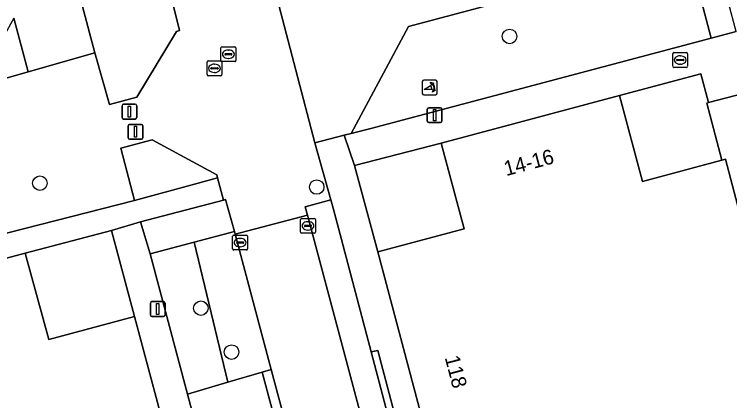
# Model space of a CAD drawing. Extents: x 162542 to 163147, y 380779 to 381521.
# Drawn here: x 162623.92 to 162672.17, y 381152.86 to 381178.9 of the extents above; entities that cross this region are included whole.
import ezdxf

# ---------------------------------------------------------------- set-up
doc = ezdxf.new("R2010")
doc.units = 0
for name, color, linetype in [('IMGEO_Afsluitpaal', 7, 'Continuous'), ('IMGEO_Boom', 7, 'Continuous'), ('IMGEO_Brandkraan', 7, 'Continuous'), ('IMGEO_Erf', 7, 'Continuous'), ('IMGEO_Groenvoorziening', 7, 'Continuous'), ('IMGEO_Kolk', 7, 'Continuous'), ('IMGEO_Lichtmast', 7, 'Continuous'), ('IMGEO_Muur', 7, 'Continuous'), ('IMGEO_Pand', 7, 'Continuous'), ('IMGEO_Pand_nummerreeks', 7, 'Continuous'), ('IMGEO_Parkeervlak_open', 7, 'Continuous'), ('IMGEO_Poller', 7, 'Continuous'), ('IMGEO_Rijbaan_lokaal_open', 7, 'Continuous'), ('IMGEO_Rioolput', 7, 'Continuous'), ('IMGEO_Voetpad_open', 7, 'Continuous')]:
    doc.layers.add(name, color=color, linetype=linetype)

msp = doc.modelspace()

# ---------------------------------------------------------------- linework, layer by layer
at = {"layer": 'IMGEO_Afsluitpaal'}
for p, q in [((162631.183, 381171.945), (162631.183, 381172.745)), ((162631.183, 381172.745), (162631.183, 381171.945)), ((162631.283, 381172.845), (162632.073, 381172.845)), ((162632.073, 381172.845), (162631.283, 381172.845)), ((162632.173, 381172.745), (162632.173, 381171.945)), ((162632.173, 381171.945), (162632.173, 381172.745)), ((162632.073, 381171.845), (162631.283, 381171.845)), ((162631.283, 381171.845), (162632.073, 381171.845)), ((162631.697, 381171.488), (162632.487, 381171.488)), ((162632.487, 381171.488), (162631.697, 381171.488)), ((162631.597, 381170.588), (162631.597, 381171.388)), ((162631.597, 381171.388), (162631.597, 381170.588)), ((162632.587, 381171.388), (162632.587, 381170.588)), ((162632.587, 381170.588), (162632.587, 381171.388)), ((162632.487, 381170.488), (162631.697, 381170.488)), ((162631.697, 381170.488), (162632.487, 381170.488))]:
    msp.add_line(p, q, dxfattribs=at)
for points in [[(162631.603, 381172.72), (162631.753, 381172.72), (162631.753, 381171.97), (162631.603, 381171.97), (162631.603, 381172.72)], [(162632.017, 381171.363), (162632.167, 381171.363), (162632.167, 381170.613), (162632.017, 381170.613), (162632.017, 381171.363)]]:
    msp.add_lwpolyline(points, dxfattribs=at)
for centre, start, end in [((162631.283, 381172.745), 90, 180), ((162631.283, 381172.745), 90, 180), ((162632.073, 381172.745), 0, 90), ((162632.073, 381172.745), 360, 90), ((162631.283, 381171.945), 180, 270), ((162631.283, 381171.945), 180, 270), ((162632.073, 381171.945), 270, 0), ((162632.073, 381171.945), 270, 0), ((162631.697, 381171.388), 90, 180), ((162631.697, 381171.388), 90, 180), ((162632.487, 381171.388), 0, 90), ((162632.487, 381171.388), 360, 90), ((162631.697, 381170.588), 180, 270), ((162631.697, 381170.588), 180, 270), ((162632.487, 381170.588), 270, 0), ((162632.487, 381170.588), 270, 0)]:
    msp.add_arc(centre, 0.1, start, end, dxfattribs=at)
at = {"layer": 'IMGEO_Boom'}
for centre in [(162657.326, 381177.414), (162625.643, 381167.524), (162644.318, 381167.263), (162636.502, 381159.099), (162638.572, 381156.14)]:
    msp.add_circle(centre, 0.489, dxfattribs=at)
at = {"layer": 'IMGEO_Brandkraan'}
for p, q in [((162668.336, 381175.398), (162668.336, 381176.25)), ((162668.411, 381176.324), (162669.263, 381176.324)), ((162669.337, 381176.25), (162669.337, 381175.398)), ((162668.595, 381175.818), (162668.595, 381175.83)), ((162669.033, 381175.781), (162668.635, 381175.781)), ((162668.638, 381175.867), (162669.036, 381175.867)), ((162668.824, 381176.104), (162668.849, 381176.104)), ((162669.079, 381175.83), (162669.079, 381175.818)), ((162669.263, 381175.324), (162668.411, 381175.324)), ((162668.847, 381175.544), (162668.822, 381175.544))]:
    msp.add_line(p, q, dxfattribs=at)
for points in [[(162668.336, 381175.398), (162668.336, 381176.25)], [(162668.411, 381176.324), (162669.263, 381176.324)], [(162669.337, 381176.25), (162669.337, 381175.398)], [(162669.263, 381175.324), (162668.411, 381175.324)]]:
    msp.add_lwpolyline(points, dxfattribs=at)
for centre, radius, start, end in [((162668.413, 381176.248), 0.0765, 91.552, 178.448), ((162668.413, 381176.248), 0.0765, 91.552, 178.448), ((162669.261, 381176.248), 0.0765, 1.552, 88.448), ((162669.261, 381176.248), 0.0765, 1.552, 88.448), ((162668.635, 381175.827), 0.0403, 85.8775, 175.7526), ((162668.632, 381175.817), 0.0366, 178.938, 274.7102), ((162669.036, 381175.824), 0.043, 264.8664, 352.4533), ((162669.04, 381175.829), 0.0386, 1.7309, 96.639), ((162668.413, 381175.4), 0.0765, 181.552, 268.448), ((162668.413, 381175.4), 0.0765, 181.552, 268.448), ((162669.261, 381175.4), 0.0765, 271.552, 358.448), ((162669.261, 381175.4), 0.0765, 271.552, 358.448)]:
    msp.add_arc(centre, radius, start, end, dxfattribs=at)
for centre, major_axis, ratio, start_param, end_param in [((162668.823, 381175.824), (-0.387, 0.002), 0.722429, 4.712389, 7.853982), ((162668.848, 381175.824), (-0.39, 0.002), 0.717154, 1.570796, 4.712389)]:
    msp.add_ellipse(centre, major_axis=major_axis, ratio=ratio, start_param=start_param, end_param=end_param, dxfattribs=at)
at = {"layer": 'IMGEO_Erf'}
for points in [[(162670.743, 381172.955), (162670.222, 381174.901), (162664.741, 381173.435), (162666.29, 381167.639), (162671.652, 381169.072), (162670.628, 381172.925)], [(162646.862, 381168.708), (162648.45, 381162.897), (162654.253, 381164.438), (162652.708, 381170.219)], [(162630.483, 381164.337), (162624.653, 381162.805), (162626.236, 381156.981), (162632.03, 381158.534)]]:
    msp.add_lwpolyline(points, close=True, dxfattribs=at)
at = {"layer": 'IMGEO_Groenvoorziening'}
for points in [[(162632.502, 381187.604), (162626.664, 381186.379), (162629.355, 381176.297), (162630.35, 381172.815), (162632.19, 381173.314), (162634.858, 381177.742), (162635.064, 381177.813), (162634.81, 381178.822), (162634.471, 381180.17)], [(162670.936, 381177.305), (162669.386, 381183.119), (162650.506, 381178.074), (162646.633, 381170.872), (162647.97, 381171.219)], [(162636.076, 381167.451), (162637.632, 381167.876), (162637.578, 381168.082), (162633.212, 381170.434), (162631.108, 381169.893), (162632.035, 381166.352)], [(162638.813, 381164.087), (162638.764, 381164.265), (162636.059, 381163.549), (162638.324, 381154.112), (162640.636, 381154.797), (162641.237, 381154.972)], [(162636.059, 381163.549), (162633.072, 381162.758), (162635.59, 381153.303), (162638.324, 381154.112)]]:
    msp.add_lwpolyline(points, close=True, dxfattribs=at)
at = {"layer": 'IMGEO_Kolk'}
for p, q in [((162643.301, 381165.145), (162644.153, 381165.145)), ((162643.226, 381164.219), (162643.226, 381165.071)), ((162643.528, 381164.688), (162643.926, 381164.688)), ((162643.714, 381164.925), (162643.739, 381164.925)), ((162644.227, 381165.071), (162644.227, 381164.219)), ((162643.485, 381164.639), (162643.485, 381164.651)), ((162643.923, 381164.602), (162643.525, 381164.602)), ((162643.737, 381164.365), (162643.712, 381164.365)), ((162643.969, 381164.651), (162643.969, 381164.639)), ((162638.647, 381163.094), (162638.647, 381163.946)), ((162638.722, 381164.02), (162639.574, 381164.02)), ((162639.135, 381163.8), (162639.16, 381163.8)), ((162639.648, 381163.946), (162639.648, 381163.094)), ((162644.153, 381164.145), (162643.301, 381164.145)), ((162638.906, 381163.514), (162638.906, 381163.526)), ((162639.344, 381163.477), (162638.946, 381163.477)), ((162638.949, 381163.563), (162639.347, 381163.563)), ((162639.158, 381163.24), (162639.133, 381163.24)), ((162639.39, 381163.526), (162639.39, 381163.514)), ((162639.574, 381163.02), (162638.722, 381163.02))]:
    msp.add_line(p, q, dxfattribs=at)
for points in [[(162643.301, 381165.145), (162644.153, 381165.145)], [(162643.226, 381164.219), (162643.226, 381165.071)], [(162644.227, 381165.071), (162644.227, 381164.219)], [(162638.647, 381163.094), (162638.647, 381163.946)], [(162638.722, 381164.02), (162639.574, 381164.02)], [(162639.648, 381163.946), (162639.648, 381163.094)], [(162644.153, 381164.145), (162643.301, 381164.145)], [(162639.574, 381163.02), (162638.722, 381163.02)]]:
    msp.add_lwpolyline(points, dxfattribs=at)
for centre, radius, start, end in [((162643.303, 381165.069), 0.0765, 91.552, 178.448), ((162643.303, 381165.069), 0.0765, 91.552, 178.448), ((162644.151, 381165.069), 0.0765, 1.552, 88.448), ((162644.151, 381165.069), 0.0765, 1.552, 88.448), ((162643.525, 381164.648), 0.0403, 85.8775, 175.7526), ((162643.93, 381164.65), 0.0386, 1.7309, 96.639), ((162643.303, 381164.221), 0.0765, 181.552, 268.448), ((162643.303, 381164.221), 0.0765, 181.552, 268.448), ((162643.522, 381164.638), 0.0366, 178.938, 274.7102), ((162643.926, 381164.645), 0.043, 264.8664, 352.4533), ((162644.151, 381164.221), 0.0765, 271.552, 358.448), ((162644.151, 381164.221), 0.0765, 271.552, 358.448), ((162638.724, 381163.944), 0.0765, 91.552, 178.448), ((162638.724, 381163.944), 0.0765, 91.552, 178.448), ((162639.572, 381163.944), 0.0765, 1.552, 88.448), ((162639.572, 381163.944), 0.0765, 1.552, 88.448), ((162638.946, 381163.523), 0.0403, 85.8775, 175.7526), ((162638.943, 381163.513), 0.0366, 178.938, 274.7102), ((162639.347, 381163.52), 0.043, 264.8664, 352.4533), ((162639.351, 381163.525), 0.0386, 1.7309, 96.639), ((162638.724, 381163.096), 0.0765, 181.552, 268.448), ((162638.724, 381163.096), 0.0765, 181.552, 268.448), ((162639.572, 381163.096), 0.0765, 271.552, 358.448), ((162639.572, 381163.096), 0.0765, 271.552, 358.448)]:
    msp.add_arc(centre, radius, start, end, dxfattribs=at)
for centre, major_axis, ratio, start_param, end_param in [((162643.713, 381164.645), (-0.387, 0.002), 0.722429, 4.712389, 7.853982), ((162643.738, 381164.645), (-0.39, 0.002), 0.717154, 1.570796, 4.712389), ((162639.134, 381163.52), (-0.387, 0.002), 0.722429, 4.712389, 7.853982), ((162639.159, 381163.52), (-0.39, 0.002), 0.717154, 1.570796, 4.712389)]:
    msp.add_ellipse(centre, major_axis=major_axis, ratio=ratio, start_param=start_param, end_param=end_param, dxfattribs=at)
at = {"layer": 'IMGEO_Lichtmast'}
for p, q in [((162651.773, 381171.707), (162651.773, 381172.507)), ((162651.773, 381172.507), (162651.773, 381171.707)), ((162651.873, 381172.607), (162652.663, 381172.607)), ((162652.663, 381172.607), (162651.873, 381172.607)), ((162652.763, 381172.507), (162652.763, 381171.707)), ((162652.763, 381171.707), (162652.763, 381172.507)), ((162652.663, 381171.607), (162651.873, 381171.607)), ((162651.873, 381171.607), (162652.663, 381171.607)), ((162633.095, 381158.638), (162633.095, 381159.438)), ((162633.095, 381159.438), (162633.095, 381158.638)), ((162633.195, 381159.538), (162633.985, 381159.538)), ((162633.985, 381159.538), (162633.195, 381159.538)), ((162634.085, 381159.438), (162634.085, 381158.638)), ((162634.085, 381158.638), (162634.085, 381159.438)), ((162633.985, 381158.538), (162633.195, 381158.538)), ((162633.195, 381158.538), (162633.985, 381158.538))]:
    msp.add_line(p, q, dxfattribs=at)
for points in [[(162652.193, 381172.482), (162652.343, 381172.482), (162652.343, 381171.732), (162652.193, 381171.732), (162652.193, 381172.482)], [(162633.515, 381159.413), (162633.665, 381159.413), (162633.665, 381158.663), (162633.515, 381158.663), (162633.515, 381159.413)]]:
    msp.add_lwpolyline(points, dxfattribs=at)
for centre, start, end in [((162651.873, 381172.507), 90, 180), ((162651.873, 381172.507), 90, 180), ((162652.663, 381172.507), 0, 90), ((162652.663, 381172.507), 360, 90), ((162651.873, 381171.707), 180, 270), ((162651.873, 381171.707), 180, 270), ((162652.663, 381171.707), 270, 0), ((162652.663, 381171.707), 270, 0), ((162633.195, 381159.438), 90, 180), ((162633.195, 381159.438), 90, 180), ((162633.985, 381159.438), 0, 90), ((162633.985, 381159.438), 360, 90), ((162633.195, 381158.638), 180, 270), ((162633.195, 381158.638), 180, 270), ((162633.985, 381158.638), 270, 0), ((162633.985, 381158.638), 270, 0)]:
    msp.add_arc(centre, 0.1, start, end, dxfattribs=at)
at = {"layer": 'IMGEO_Muur'}
for points in [[(162664.741, 381173.435), (162670.222, 381174.901), (162670.743, 381172.955)], [(162648.45, 381162.897), (162646.862, 381168.708), (162652.708, 381170.219)], [(162624.653, 381162.805), (162630.483, 381164.337)], [(162630.483, 381164.337), (162632.03, 381158.534)]]:
    msp.add_lwpolyline(points, dxfattribs=at)
at = {"layer": 'IMGEO_Pand'}
for points in [[(162671.652, 381169.072), (162671.893, 381169.137), (162673.417, 381163.326), (162673.663, 381163.392), (162678.64, 381164.714), (162676.111, 381174.362), (162670.743, 381172.955), (162670.628, 381172.925)], [(162671.652, 381169.072), (162666.29, 381167.639), (162664.741, 381173.435), (162652.708, 381170.219), (162654.253, 381164.438), (162648.45, 381162.897), (162651.526, 381151.298), (162653.181, 381145.057), (162656.081, 381145.826), (162665.799, 381148.416), (162673.828, 381150.554), (162676.822, 381151.351), (162676.015, 381154.427), (162675.228, 381157.426), (162673.663, 381163.392), (162673.417, 381163.326), (162671.893, 381169.137)], [(162612.385, 381137.285), (162613.138, 381134.433), (162616.382, 381135.289), (162624.218, 381137.357), (162633.868, 381139.932), (162636.792, 381140.677), (162635.122, 381146.939), (162632.03, 381158.534), (162626.236, 381156.981), (162624.653, 381162.805), (162621.772, 381162.037), (162612.654, 381159.607), (162614.19, 381153.803), (162608.82, 381152.374), (162608.616, 381152.32), (162610.393, 381145.637), (162610.195, 381145.585), (162611.492, 381140.668), (162611.654, 381140.055)]]:
    msp.add_lwpolyline(points, close=True, dxfattribs=at)
at = {"layer": 'IMGEO_Parkeervlak_open'}
for points in [[(162647.981, 381156.163), (162645.785, 381164.499), (162645.416, 381165.832), (162645.26, 381166.395), (162643.543, 381165.92), (162643.686, 381165.375), (162649.38, 381144.042), (162651.083, 381144.497), (162649.522, 381150.353)], [(162640.636, 381154.797), (162638.324, 381154.112), (162635.59, 381153.303), (162637.327, 381146.78), (162639.72, 381147.43), (162642.421, 381148.163)]]:
    msp.add_lwpolyline(points, close=True, dxfattribs=at)
at = {"layer": 'IMGEO_Poller'}
for p, q in [((162651.439, 381174.38), (162651.439, 381173.573)), ((162651.439, 381174.38), (162651.439, 381173.573)), ((162652.341, 381174.475), (162651.533, 381174.475)), ((162652.341, 381174.475), (162651.533, 381174.475)), ((162652.435, 381173.573), (162652.435, 381174.38)), ((162652.435, 381173.573), (162652.435, 381174.38)), ((162651.533, 381173.478), (162652.341, 381173.478)), ((162651.533, 381173.478), (162652.341, 381173.478))]:
    msp.add_line(p, q, dxfattribs=at)
for points in [[(162652.118, 381174.204), (162652.106, 381174.131), (162651.981, 381174.336)], [(162651.981, 381174.336), (162652.212, 381174.27), (162652.141, 381174.238)], [(162652.074, 381173.831), (162651.561, 381173.831), (162651.991, 381174.106)], [(162652.134, 381173.659), (162652.2, 381173.89), (162652.23, 381173.822)], [(162652.266, 381173.795), (162652.338, 381173.784), (162652.134, 381173.659)]]:
    msp.add_lwpolyline(points, dxfattribs=at)
for centre, radius, start, end in [((162651.533, 381174.38), 0.0946, 90, 180), ((162651.533, 381174.38), 0.0946, 90, 180), ((162652.341, 381174.38), 0.0946, 0, 90), ((162652.341, 381174.38), 0.0946, 0, 90), ((162651.746, 381173.881), 0.332, 351.3247, 42.4854), ((162651.76, 381173.891), 0.476, 351.7527, 41.1691), ((162651.76, 381173.891), 0.516, 349.3569, 42.2912), ((162651.533, 381173.573), 0.0946, 180, 270), ((162651.533, 381173.573), 0.0946, 180, 270), ((162652.341, 381173.573), 0.0946, 270, 0), ((162652.341, 381173.573), 0.0946, 270, 0)]:
    msp.add_arc(centre, radius, start, end, dxfattribs=at)
at = {"layer": 'IMGEO_Rijbaan_lokaal_open'}
for points in [[(162634.471, 381180.17), (162634.81, 381178.822), (162635.064, 381177.813), (162634.858, 381177.742), (162632.19, 381173.314), (162630.35, 381172.815), (162629.355, 381176.297), (162624.853, 381175.019), (162619.18, 381173.408)], [(162621.347, 381163.631), (162632.035, 381166.352), (162631.108, 381169.893), (162633.212, 381170.434), (162637.578, 381168.082), (162637.632, 381167.876), (162638.026, 381166.382), (162638.175, 381166.421), (162638.764, 381164.265), (162638.813, 381164.087), (162643.686, 381165.375), (162643.543, 381165.92), (162645.26, 381166.395), (162644.195, 381170.241), (162641.762, 381179.517)], [(162649.38, 381144.042), (162643.686, 381165.375), (162638.813, 381164.087), (162641.237, 381154.972), (162643.024, 381148.328)]]:
    msp.add_lwpolyline(points, dxfattribs=at)
at = {"layer": 'IMGEO_Rioolput'}
for p, q in [((162637.859, 381175.787), (162637.859, 381176.639)), ((162637.934, 381176.713), (162638.786, 381176.713)), ((162638.161, 381176.256), (162638.559, 381176.256)), ((162638.347, 381176.493), (162638.372, 381176.493)), ((162638.86, 381176.639), (162638.86, 381175.787)), ((162636.992, 381175.763), (162637.844, 381175.763)), ((162638.118, 381176.207), (162638.118, 381176.219)), ((162638.556, 381176.17), (162638.158, 381176.17)), ((162638.37, 381175.933), (162638.345, 381175.933)), ((162638.602, 381176.219), (162638.602, 381176.207)), ((162636.917, 381174.837), (162636.917, 381175.689)), ((162637.219, 381175.306), (162637.617, 381175.306)), ((162637.405, 381175.543), (162637.43, 381175.543)), ((162637.918, 381175.689), (162637.918, 381174.837)), ((162638.786, 381175.713), (162637.934, 381175.713)), ((162637.176, 381175.257), (162637.176, 381175.269)), ((162637.614, 381175.22), (162637.216, 381175.22)), ((162637.428, 381174.983), (162637.403, 381174.983)), ((162637.66, 381175.269), (162637.66, 381175.257)), ((162637.844, 381174.763), (162636.992, 381174.763))]:
    msp.add_line(p, q, dxfattribs=at)
for points in [[(162637.859, 381175.787), (162637.859, 381176.639)], [(162637.934, 381176.713), (162638.786, 381176.713)], [(162638.86, 381176.639), (162638.86, 381175.787)], [(162636.992, 381175.763), (162637.844, 381175.763)], [(162636.917, 381174.837), (162636.917, 381175.689)], [(162637.918, 381175.689), (162637.918, 381174.837)], [(162638.786, 381175.713), (162637.934, 381175.713)], [(162637.844, 381174.763), (162636.992, 381174.763)]]:
    msp.add_lwpolyline(points, dxfattribs=at)
for centre, radius, start, end in [((162637.936, 381176.637), 0.0765, 91.552, 178.448), ((162637.936, 381176.637), 0.0765, 91.552, 178.448), ((162638.158, 381176.216), 0.0403, 85.8775, 175.7526), ((162638.563, 381176.218), 0.0386, 1.7309, 96.639), ((162638.784, 381176.637), 0.0765, 1.552, 88.448), ((162638.784, 381176.637), 0.0765, 1.552, 88.448), ((162636.994, 381175.687), 0.0765, 91.552, 178.448), ((162636.994, 381175.687), 0.0765, 91.552, 178.448), ((162637.842, 381175.687), 0.0765, 1.552, 88.448), ((162637.842, 381175.687), 0.0765, 1.552, 88.448), ((162637.936, 381175.789), 0.0765, 181.552, 268.448), ((162637.936, 381175.789), 0.0765, 181.552, 268.448), ((162638.155, 381176.206), 0.0366, 178.938, 274.7102), ((162638.559, 381176.213), 0.043, 264.8664, 352.4533), ((162638.784, 381175.789), 0.0765, 271.552, 358.448), ((162638.784, 381175.789), 0.0765, 271.552, 358.448), ((162637.216, 381175.266), 0.0403, 85.8775, 175.7526), ((162637.621, 381175.268), 0.0386, 1.7309, 96.639), ((162636.994, 381174.839), 0.0765, 181.552, 268.448), ((162636.994, 381174.839), 0.0765, 181.552, 268.448), ((162637.213, 381175.256), 0.0366, 178.938, 274.7102), ((162637.617, 381175.263), 0.043, 264.8664, 352.4533), ((162637.842, 381174.839), 0.0765, 271.552, 358.448), ((162637.842, 381174.839), 0.0765, 271.552, 358.448)]:
    msp.add_arc(centre, radius, start, end, dxfattribs=at)
for centre, major_axis, ratio, start_param, end_param in [((162638.346, 381176.213), (-0.387, 0.002), 0.722429, 4.712389, 7.853982), ((162638.371, 381176.213), (-0.39, 0.002), 0.717154, 1.570796, 4.712389), ((162637.404, 381175.263), (-0.387, 0.002), 0.722429, 4.712389, 7.853982), ((162637.429, 381175.263), (-0.39, 0.002), 0.717154, 1.570796, 4.712389)]:
    msp.add_ellipse(centre, major_axis=major_axis, ratio=ratio, start_param=start_param, end_param=end_param, dxfattribs=at)
at = {"layer": 'IMGEO_Voetpad_open'}
for points in [[(162623.896, 381178.638), (162624.853, 381175.019), (162629.355, 381176.297), (162626.664, 381186.379), (162624.433, 381194.739), (162624.216, 381195.549), (162622.148, 381203.299), (162624.69, 381205.627), (162625.273, 381206.161), (162630.092, 381210.576), (162660.951, 381239.561), (162662.218, 381238.238), (162662.638, 381238.636), (162665.881, 381241.702)], [(162678.158, 381189.24), (162654.703, 381182.974), (162653.633, 381182.688), (162643.831, 381180.07), (162641.697, 381179.759), (162641.762, 381179.517), (162644.195, 381170.241), (162646.164, 381170.751), (162646.633, 381170.872), (162650.506, 381178.074), (162669.386, 381183.119), (162670.936, 381177.305), (162672.612, 381177.749), (162671.064, 381183.564), (162697.537, 381190.645)], [(162672.612, 381177.749), (162670.936, 381177.305), (162647.97, 381171.219), (162646.633, 381170.872), (162646.164, 381170.751), (162646.862, 381168.708), (162652.708, 381170.219), (162664.741, 381173.435), (162670.222, 381174.901), (162670.743, 381172.955), (162676.111, 381174.362)]]:
    msp.add_lwpolyline(points, dxfattribs=at)
for points in [[(162605.985, 381169.742), (162619.18, 381173.408), (162624.853, 381175.019), (162623.896, 381178.638), (162622.704, 381176.538), (162608.579, 381172.64), (162603.602, 381171.296), (162600.724, 381170.519), (162595.603, 381169.137), (162595.636, 381169.014), (162594.296, 381168.647), (162588.744, 381167.128), (162571.831, 381162.454), (162568.023, 381161.469), (162567.663, 381161.371), (162568.211, 381159.383), (162569.139, 381159.638), (162600.111, 381168.166)], [(162648.45, 381162.897), (162646.862, 381168.708), (162646.164, 381170.751), (162644.195, 381170.241), (162645.26, 381166.395), (162645.416, 381165.832), (162645.785, 381164.499), (162647.981, 381156.163), (162648.438, 381156.257), (162649.973, 381150.456), (162649.522, 381150.353), (162651.083, 381144.497), (162653.181, 381145.057), (162651.526, 381151.298)], [(162632.437, 381164.912), (162638.026, 381166.382), (162637.632, 381167.876), (162636.076, 381167.451), (162632.035, 381166.352), (162621.347, 381163.631), (162621.772, 381162.037), (162624.653, 381162.805), (162630.483, 381164.337)], [(162638.175, 381166.421), (162638.026, 381166.382), (162632.437, 381164.912), (162633.072, 381162.758), (162636.059, 381163.549), (162638.764, 381164.265)], [(162645.063, 381117.734), (162643.311, 381124.312), (162640.435, 381135.109), (162640.133, 381136.243), (162637.327, 381146.78), (162635.59, 381153.303), (162633.072, 381162.758), (162632.437, 381164.912), (162630.483, 381164.337), (162632.03, 381158.534), (162635.122, 381146.939), (162636.792, 381140.677), (162639.746, 381129.54), (162641.278, 381123.741), (162644.458, 381111.704), (162646.014, 381105.912), (162648.066, 381106.457)], [(162647.981, 381156.163), (162649.522, 381150.353), (162649.973, 381150.456), (162648.438, 381156.257)], [(162641.237, 381154.972), (162640.636, 381154.797), (162642.421, 381148.163), (162643.024, 381148.328)]]:
    msp.add_lwpolyline(points, close=True, dxfattribs=at)

# ---------------------------------------------------------------- texts
at = {"layer": 'IMGEO_Pand_nummerreeks'}
for s, rotation, p in [('14-16', 14.9655, (162657.095, 381167.996)), ('118', 284.8518, (162652.946, 381155.772))]:
    msp.add_text(s, height=1, rotation=rotation, dxfattribs=at).set_placement(p)

doc.saveas('drawing.dxf')
